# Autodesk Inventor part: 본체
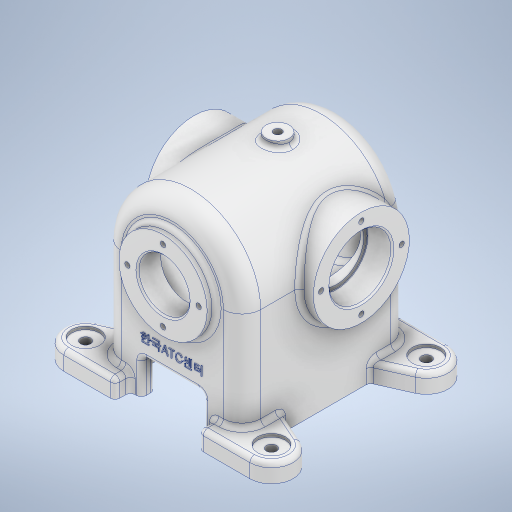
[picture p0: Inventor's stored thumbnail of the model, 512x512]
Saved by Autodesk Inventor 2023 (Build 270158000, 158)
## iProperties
Created: 2024-09
Part Number: 본체
Material: 알루미늄 6061
Document SubType Name: Modeling
Designer: asung
Density: 2.7 g/cm^3
Appearance: 알루미늄 - 평지
Mass: 1386.18 g
Surface Area: 1150.11 cm^2
Volume: 513.4 cm^3
Author: asung
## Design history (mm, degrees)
sketch "스케치1"
  geometry: L1 (-45, -38)-(45, -38); L2 (45, -38)-(45, 38); L3 (45, 38)-(-45, 38); L4 (-45, 38)-(-45, -38); L5 (-45, -38)-(45, 38); L6 (45, -38)-(-45, 38); 3 further points
  constraints: 12 end point, 3 midpoint, 2 parallel, 1 horizontal, 1 perpendicular, 3 other
  dimensions: "d0" = 90 distance of L3.end L2.end; "d1" = 76 distance of L2.end L1.end
extrude "돌출1" new body sketch "스케치1" stored distance "d2" = 108; taper "d3" = 0 deg
sketch "스케치2"
  geometry: L1 (-45, 38)-(-45, -38) reference; L2 (-45, -38)-(45, -38) reference; L3 (45, -38)-(45, 38) reference; L4 (-20, -38)-(20, -38); L5 (20, -38)-(20, -15); L6 (20, -15)-(-20, -15); L7 (-20, -15)-(-20, -38); A1 r 45 centre (0, 38) between (45, 38) and (-45, 38) reference; 2 further points
  constraints: 8 end point, 2 parallel, 1 horizontal, 1 perpendicular, 1 point on line
  dimensions: "d4" = 40 distance of L6.end L5.end; "d5" = 23 distance of L5.end L4.end; "d6" = 25 distance between parallel lines of L1 L7
extrude "돌출2" cut sketch "스케치2" stored distance "d7" = 108; taper "d8" = 0 deg
feature "쉘1" dims "d9" = 9
sketch "스케치3"
  geometry: C1 r 45 at (0, 38); A1 r 36 centre (0, 38) between (36, 38) and (-36, 38) reference; 1 further point
  constraints: 1 centre point, 1 coincident
extrude "돌출3" join sketch "스케치3" distance "d10" = 108; taper "d11" = 0 deg
sketch "스케치4"
  geometry: L1 (-45, 38)-(-45, -38) reference; L2 (-45, -38)-(-20, -38) reference; L3 (-20, -38)-(-20, -15) reference; L4 (-20, -15)-(20, -15) reference; L5 (20, -15)-(20, -38) reference; L6 (20, -38)-(45, -38) reference; L7 (45, -38)-(45, 38) reference; C1 r 28.5 at (0, 38); A1 r 45 centre (0, 38) between (45, 38) and (-45, 38) reference; 1 further point
  constraints: 1 centre point, 1 coincident
  dimensions: "d12" = 57 diameter of C1
extrude "돌출4" join sketch "스케치4" distance "d13" = 6; taper "d14" = 0 deg
sketch "스케치5"
  geometry: L1 (-7, -45)-(-7, 45) reference; L2 (-7, 45)-(-15, 45) reference; L3 (-15, 45)-(-15, 54) reference; L4 (-15, 54)-(9.5, 54) reference; L5 (9.5, 54)-(9.5, 60) reference; L6 (9.5, 60)-(66.5, 60) reference; L7 (66.5, 60)-(66.5, 54) reference; L8 (66.5, 54)-(83, 54) reference; L9 (83, 54)-(83, -54) reference; L10 (83, -54)-(-15, -54) reference; L11 (-15, -54)-(-15, -45) reference; L12 (-15, -45)-(-7, -45) reference; L13 (66.5, 60)-(9.5, 60) reference; L14 (38, -54)-(-38, -54) reference; L15 (38, 60)-(38, -54); L16 (38, -54)-(38, 54) reference; L17 (38, -45)-(71, -45); L18 (74, -42)-(74, 42); L19 (71, 45)-(54.5, 45); L20 (54.5, 45)-(54.5, 60); A1 r 3 centre (71, -42) between (71, -45) and (74, -42); A2 r 3 centre (71, 42) between (74, 42) and (71, 45); 4 further points
  constraints: 10 end point, 4 perpendicular, 4 point on circle, 4 tangent, 2 centre point, 2 point on line, 1 equal radius, 1 horizontal, 1 midpoint
  dimensions: "d15" = 9 distance between parallel lines of L10 L17; "d16" = 9 distance between parallel lines of L18 L9; "d17" = 9 distance between parallel lines of L8 L19; "d18" = 16.5 distance from line of L16.end L20; "d19" = 3 radius of A1
revolve "회전1" sketch "스케치5" stored, may be unused: angle "d20" = 90 deg
chamfer "모따기1" distance "d21" = 1; stored, may be unused: second distance "d22" = 2, angle "d23" = 45 deg
node "작업 평면1"
sketch "스케치6"
  geometry: L1 (-38, -54)-(-38, 54) reference; L2 (66.5, 60)-(9.5, 60) reference; C1 r 31 at (38, -14); 1 further point
  constraints: 1 centre point
  dimensions: "d25" = 62 diameter of C1; "d26" = 76 distance from line of L1 C1.centre; "d27" = 74 distance from line of C1.centre L2
extrude "돌출5" join sketch "스케치6" stored distance "d28" = 6; taper "d29" = 0 deg
sketch "스케치7"
  geometry: C1 r 31 at (0, 0) reference; 2 further points
  constraints: 1 coincident
hole "구멍1" sketch "스케치7" at (0, 0) diameter "d30" = 35; stored, may be unused: countersink angle "d34" = 90 deg, drill point angle "d36" = 0 deg; dims "d31" = 6, "d32" = 40, "d33" = 16, "d35" = 50
sketch "스케치8"
  geometry: C1 r 31 at (0, 0) reference; 2 further points
  constraints: 1 coincident
hole "구멍2" sketch "스케치8" at (0, 0) diameter "d37" = 35; stored, may be unused: countersink angle "d41" = 90 deg, drill point angle "d43" = 0 deg; dims "d38" = 6, "d39" = 40, "d40" = 16, "d42" = 50
chamfer "모따기2" distance "d44" = 1; stored, may be unused: second distance "d45" = 2, angle "d46" = 45 deg
fillet "모깎기1" dims "d47" = 0.3
node "작업 평면2"
sketch "스케치9"
  geometry: L1 (-9, 9)-(-9, 71) reference; L2 (73.5, 114)-(16.5, 114) reference; C1 r 7.5 at (45, 40); 1 further point
  constraints: 1 centre point
  dimensions: "d49" = 15 diameter of C1; "d50" = 54 distance from line of L1 C1.centre; "d51" = 74 distance from line of L2 C1.centre
extrude "돌출6" join sketch "스케치9" stored distance "d52" = 10; taper "d53" = 0 deg
sketch "스케치10"
  geometry: C1 r 7.5 at (0, 0) reference; 2 further points
  constraints: 1 coincident
hole "구멍3" sketch "스케치10" at (0, 0) diameter "d54" = 5.1881; stored, may be unused: countersink angle "d58" = 90 deg, drill point angle "d60" = 0 deg; dims "d55" = 20, "d56" = 40, "d57" = 16, "d59" = 20
fillet "모깎기2" dims "d61" = 12
fillet "모깎기3" dims "d62" = 3
sketch "스케치11" dims "d63" = 46
  geometry: C1 r 28.5 at (0, 0) reference; C2 r 17.5 at (0, 0) reference; 3 further points
  constraints: 1 coincident, 1 vertical alignment, 2 other
hole "구멍4" sketch "스케치11" at (0, 23) diameter "d64" = 3.45873; stored, may be unused: countersink angle "d68" = 90 deg, drill point angle "d70" = 118 deg; dims "d65" = 8, "d66" = 4, "d67" = 2, "d69" = 10
sketch "스케치12" dims "d74" = 52
  geometry: C1 r 31 at (0, 0) reference; C2 r 21 at (0, 0) reference; 3 further points
  constraints: 1 coincident, 1 vertical alignment, 2 other
hole "구멍5" sketch "스케치12" at (0, 26) diameter "d75" = 3.45873; stored, may be unused: countersink angle "d79" = 90 deg, drill point angle "d81" = 118 deg; dims "d76" = 8, "d77" = 4, "d78" = 2, "d80" = 10
fillet "모깎기4" dims "d85" = 3
node "작업 평면5"
sketch "스케치14"
  geometry: L1 (-28.5, -74)-(28.5, -74) reference; C1 r 7.5 at (0, 0); 1 further point
  constraints: 1 centre point, 1 vertical alignment
  dimensions: "d90" = 15 diameter of C1; "d91" = 74 distance from line of L1 C1.centre
extrude "돌출7" join sketch "스케치14" stored distance "d92" = 10; taper "d93" = 0 deg
sketch "스케치15"
  geometry: C1 r 7.5 at (0, 0) reference; 2 further points
  constraints: 1 coincident
hole "구멍6" sketch "스케치15" at (0, 0) diameter "d94" = 5.1881; stored, may be unused: countersink angle "d98" = 90 deg, drill point angle "d100" = 118 deg; dims "d95" = 20, "d96" = 4, "d97" = 2, "d99" = 20
fillet "모깎기5" dims "d101" = 3
sketch "스케치16"
  geometry: L1 (40, -95)-(-80, -95); L2 (-80, -95)-(-80, 5); L3 (-80, 5)-(40, 5); L4 (40, 5)-(40, -95); L5 (40, -95)-(-80, 5); L6 (-80, -95)-(40, 5); L7 (-40, -99)-(-53, -99) reference; L8 (-40, -99)-(-40, -90) reference; L9 (-40, -90)-(-56, -90) reference; L10 (-56, -90)-(-56, 0) reference; L11 (-56, 0)-(-40, 0) reference; L12 (-40, 0)-(-40, 9) reference; L13 (-53, 9)-(-40, 9) reference; L14 (-65, -87)-(-65, -3) reference; L15 (25, -87)-(25, -3) reference; L16 (0, 9)-(13, 9) reference; L17 (0, 9)-(0, 0) reference; L18 (0, 0)-(16, 0) reference; L19 (16, 0)-(16, -90) reference; L20 (16, -90)-(0, -90) reference; L21 (0, -90)-(0, -99) reference; L22 (13, -99)-(0, -99) reference; L23 (-65, -25)-(-65, -87) reference; L24 (-85.693, -82.21)-(-65, -73); L25 (-80, -109)-(-47, -109); L26 (-47, -109)-(-47, -99); L27 (0, -99)-(-40, -99) reference; L28 (-20, -99)-(-20, -116.637); L29 (45.693, -82.21)-(25, -73); L30 (40, -109)-(7, -109); L31 (-80, -95)-(40, -95); L32 (40, -95)-(40, 5); L33 (40, -95)-(-80, 5); L34 (7, -109)-(7, -99); L35 (-20, -45)-(-37.912, -45); L36 (-85.693, -7.79)-(-65, -17); L37 (-80, 19)-(-47, 19); L38 (-47, 19)-(-47, 9); L39 (7, 19)-(7, 9); L40 (40, 19)-(7, 19); L41 (45.693, -7.79)-(25, -17); A1 r 12 centre (-53, -87) between (-65, -87) and (-53, -99) reference; A2 r 12 centre (-53, -3) between (-53, 9) and (-65, -3) reference; A3 r 12 centre (13, -87) between (13, -99) and (25, -87) reference; A4 r 12 centre (13, -3) between (25, -3) and (13, 9) reference; A5 r 14 centre (-80, -95) between (-85.693, -82.21) and (-80, -109); A6 r 14 centre (40, -95) between (45.693, -82.21) and (40, -109); A7 r 14 centre (-80, 5) between (-85.693, -7.79) and (-80, 19); A8 r 14 centre (40, 5) between (45.693, -7.79) and (40, 19); 7 further points
  constraints: 46 end point, 22 symmetric about line, 8 point on circle, 4 centre point, 3 horizontal, 3 midpoint, 2 coincident, 2 parallel, 2 perpendicular, 2 point on line, 2 tangent, 1 vertical, 3 other
  dimensions: "d102" = 120 distance of L2.end L3.end; "d103" = 100 distance of L1.end L2.end; "d104" = 14 radius of A5; "d107" = 36 distance from line of L25 L24.end; "d108" = 18 distance between parallel lines of L23 L26
extrude "돌출8" join sketch "스케치16" distance "d109" = 12; taper "d110" = 0 deg
sketch "스케치17"
  geometry: A1 r 14 centre (40, -5) between (40, -19) and (45.693, 7.79) reference; A2 r 14 centre (40, 95) between (45.693, 82.21) and (40, 109) reference; A3 r 14 centre (-80, -5) between (-85.693, 7.79) and (-80, -19) reference; A4 r 14 centre (-80, 95) between (-80, 109) and (-85.693, 82.21) reference; 5 further points
  constraints: 4 coincident
hole "구멍7" sketch "스케치17" at (40, -5), (40, 95), (-80, -5), (-80, 95) diameter "d111" = 6.6; stored, may be unused: countersink angle "d115" = 90 deg, drill point angle "d117" = 0 deg; dims "d112" = 20, "d113" = 18, "d114" = 2, "d116" = 12
fillet "모깎기6" dims "d118" = 3
fillet "모깎기7" dims "d119" = 3
fillet "모깎기8" dims "d120" = 3
fillet "모깎기9" dims "d121" = 3
sketch "스케치18"
  geometry: L1 (-30, -38)-(-60, -38) reference; C1 r 33 at (0, 38) reference; 2 further points
  constraints: 1 vertical alignment, 1 other
  dimensions: "d122" = 35 distance from line of L1 point (0, -3)
feature "엠보싱1" sketch "스케치18" dims "d123" = 0.5, "d124" = 0
fillet "모깎기10" dims "d125" = 3
fillet "모깎기11" dims "d126" = 3
fillet "모깎기12" dims "d127" = 3
fillet "모깎기13" dims "d128" = 3
feature "ڎ耀ڐ耀ڒ耀ڔ耀ږ耀ژ耀ښ耀ڜ耀" dims "d0" = 90, "d1" = 76, "d2" = 108, "d3" = 0, "d4" = 40, "d5" = 23, "d6" = 25, "d7" = 108, "d8" = 0, "d9" = 9, "d10" = 108, "d11" = 0, "d12" = 57, "d13" = 6, "d14" = 0, "d15" = 9, "d16" = 9, "d17" = 9, "d18" = 16.5, "d19" = 3, "d20" = 90 deg, "d21" = 1, "d22" = 2, "d23" = 45 deg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
feature "۠耀ۢ耀ۤ耀ۦ耀ۨ耀۪耀۬耀ۮ耀" dims "d0" = 90, "d1" = 76, "d2" = 108, "d3" = 0, "d4" = 40, "d5" = 23, "d6" = 25, "d7" = 108, "d8" = 0, "d9" = 9, "d10" = 108, "d11" = 0, "d12" = 57, "d13" = 6, "d14" = 0, "d15" = 9, "d16" = 9, "d17" = 9, "d18" = 16.5, "d19" = 3, "d20" = 90 deg, "d21" = 1, "d22" = 2, "d23" = 45 deg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
node "솔리드1"
mirror "미러1"
pattern_circular "원형 패턴1" dims angle "d72" = 360 deg
pattern_circular "원형 패턴2" dims angle "d83" = 360 deg
mirror "미러2"
node "투영된 루프1"
node "투영된 루프2"
node "투영된 루프3"
node "투영된 루프4"
node "투영된 루프5"
node "투영된 루프6"
node "투영된 루프7"
node "절단 모서리 투영1"
feature "A9D066F2-1C7D-4E18-AEED-F7BC21143FA4" dims "d30" = 35, "d31" = 6, "d32" = 40, "d33" = 16, "d34" = 90 deg, "d35" = 50, "d36" = 0
